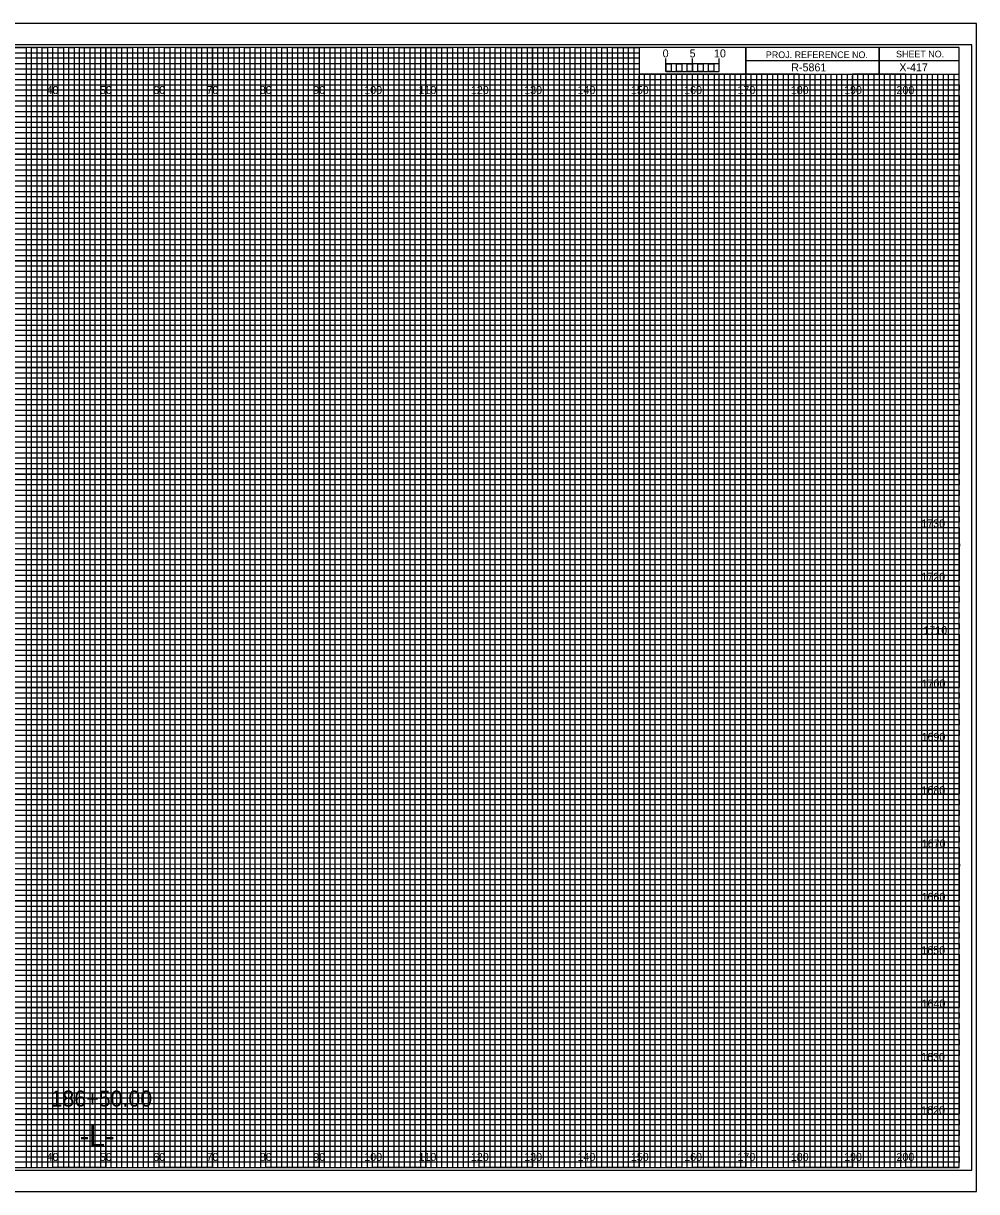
# Model space of a CAD drawing. Extents: x -13 to 323, y -5 to 6154.
# Drawn here: x 144.5 to 323.3, y 2855.5 to 3074.5 of the extents above; entities that cross this region are included whole.
import ezdxf

# ---------------------------------------------------------------- set-up
doc = ezdxf.new("R2010")
doc.units = 0
for name, color, linetype in [('Exist CMT Ground Line', 7, 'Continuous'), ('Prop Horizontal Alignment', 7, 'Continuous'), ('Prop Retaining Wall', 7, 'Continuous'), ('Prop XS Alignment Label', 7, 'Continuous'), ('Prop XS Bar Scale Labels', 7, 'Continuous'), ('Prop XS DDE', 7, 'Continuous'), ('Prop XS DDE Elevations', 7, 'Continuous'), ('Prop XS DDE Slope Text', 7, 'Continuous'), ('Prop XS Earthwork Shape', 7, 'Continuous'), ('Prop XS Elevation Labels', 7, 'Continuous'), ('Prop XS Project Number', 7, 'Continuous'), ('Prop XS Sheet Number', 7, 'Continuous'), ('Prop XS Station Labels', 7, 'Continuous'), ('Raster_Level_0', 7, 'Continuous'), ('Scratch_Level_3', 7, 'Continuous'), ('Sheet Cutting Line CELL', 7, 'Continuous')]:
    doc.layers.add(name, color=color, linetype=linetype)

msp = doc.modelspace()

# ---------------------------------------------------------------- linework, layer by layer
at = {"layer": 'Exist CMT Ground Line'}
for p, q in [((265, 3065.49), (265, 3067.9)), ((265, 3066.9), (265, 3067.9)), ((270, 3065.49), (270, 3067.9)), ((275, 3065.49), (275, 3067.9)), ((275, 3066.9), (275, 3067.9))]:
    msp.add_line(p, q, dxfattribs=at)
for points in [[(275, 3066.9), (265, 3066.9), (265, 3065.49), (275, 3065.49)], [(265, 3066.9), (266, 3066.9), (266, 3065.49), (265, 3065.49)], [(267, 3066.9), (268, 3066.9), (268, 3065.49), (267, 3065.49)], [(269, 3066.9), (270, 3066.9), (270, 3065.49), (269, 3065.49)], [(271, 3066.9), (272, 3066.9), (272, 3065.49), (271, 3065.49)], [(273, 3066.9), (274, 3066.9), (274, 3065.49), (273, 3065.49)]]:
    msp.add_lwpolyline(points, close=True, dxfattribs=at)
at = {"layer": 'Prop Retaining Wall'}
for p, q in [((0, 3069), (260, 3069)), ((260, 3069), (260, 3067.98)), ((260, 3067.98), (0, 3067.98)), ((0, 3067), (260, 3067)), ((260, 3067), (260, 3065.89)), ((260, 3065.89), (0, 3065.89)), ((0, 3064), (320, 3064))]:
    msp.add_line(p, q, dxfattribs=at)
for points in [[(0, 3063), (270, 3063), (320, 3063), (320, 3062), (0, 3062)], [(0, 3061), (320, 3061), (320, 3059), (0, 3059)], [(0, 3058), (320, 3058), (320, 3057), (0, 3056.98)], [(0, 3056), (320, 3056), (320, 3054), (0, 3054)], [(0, 3053), (320, 3053), (320, 3052), (0, 3052)], [(0, 3051), (320, 3051), (320, 3049), (0, 3049)], [(0, 3048), (320, 3048), (320, 3047), (0, 3047)], [(0, 3046), (320, 3046), (320, 3044), (0, 3044)], [(0, 3043), (320, 3043), (320, 3042), (0, 3042)], [(0, 3041), (320, 3041), (320, 3039), (0, 3039)], [(0, 3038), (320, 3038), (320, 3037), (0, 3037)], [(0, 3036), (320, 3036), (320, 3033.95), (320, 3033), (320, 3032), (0, 3032)], [(0, 3034), (320, 3034), (320, 3033), (0, 3033)], [(0, 3031), (320, 3031), (320, 3029), (0, 3029.03)], [(0, 3029.03), (320, 3029), (320, 3028), (0, 3028)], [(0, 3027), (320, 3027), (320, 3026), (0, 3026)], [(0, 3024), (320, 3024), (320, 3023), (0, 3023)], [(0, 3022), (320, 3022), (320, 3021), (0, 3021)], [(-0.07, 3018.89), (320, 3018.89), (320, 3017.88), (-0.07, 3017.88)], [(0, 3017), (320, 3017), (320, 3016), (0, 3016)], [(0, 3014), (320, 3014), (320, 3013), (0, 3013)], [(0, 3012), (320, 3012), (320, 3011), (0, 3011)], [(0, 3009), (320, 3009), (320, 3008), (0, 3008)], [(0, 3007), (320, 3007), (320, 3006), (0, 3006)], [(0, 3004), (320, 3004), (320, 3003), (0, 3003)], [(0, 3002), (320, 3002), (320, 3001), (0, 3001)], [(0, 2999), (320, 2999), (319.99, 2997.98), (0, 2998)], [(0, 2997), (320, 2997), (320, 2996), (0, 2996)], [(0, 2994), (320, 2994), (320, 2993), (0, 2993)], [(0, 2992), (320, 2992), (320, 2991), (0, 2991)], [(0, 2989), (320, 2989), (320, 2988), (0, 2988)], [(0, 2987), (320, 2987), (320, 2986), (0, 2986)], [(0, 2984), (320, 2984), (320, 2983), (0, 2983)], [(0, 2982), (320, 2982), (320, 2981), (0, 2981)], [(0, 2979), (320, 2979), (320, 2978), (0, 2978)], [(0, 2976.99), (320.07, 2976.91), (320, 2976), (0, 2976)], [(0, 2974), (320, 2974), (320, 2973), (0, 2973)], [(0, 2972), (320, 2972), (320, 2971), (0, 2971)], [(0, 2969), (320, 2969), (320, 2968), (0, 2968)], [(0, 2967), (320, 2967), (320, 2966), (0, 2966)], [(0, 2964), (320, 2964), (320, 2963), (0, 2963)], [(0, 2962), (320, 2962), (320, 2961), (0, 2961)], [(0, 2959), (320, 2959), (320, 2958), (0, 2958)], [(0, 2957), (320, 2957), (320, 2956), (0, 2956)], [(0, 2954), (320, 2954), (320, 2953), (0, 2953)], [(0, 2952), (320, 2952), (320, 2951), (0, 2951)], [(0, 2949), (320, 2949), (320, 2948), (0, 2948)], [(0, 2947), (320, 2947), (320, 2946), (0, 2946)], [(0, 2944), (320, 2944), (320, 2943), (0, 2943)], [(0, 2942), (320, 2942), (320, 2941), (0, 2941)], [(0, 2939), (320, 2939), (319.99, 2937.98), (0, 2938)], [(0, 2937), (320, 2937), (320, 2936), (0, 2936)], [(0, 2934), (320, 2934), (320, 2933), (0, 2933)], [(0, 2932), (320, 2932), (320, 2931), (0, 2931)], [(0, 2929), (320, 2929), (320, 2928), (0, 2928)], [(0, 2927), (320, 2927), (320, 2926), (0, 2926)], [(0, 2924), (320, 2924), (320, 2923), (0, 2923)], [(0, 2922), (320, 2922), (320, 2921), (0, 2921)], [(0, 2919), (320, 2919), (320, 2918), (0, 2918)], [(0, 2916.99), (320.07, 2916.91), (320, 2916), (0, 2916)], [(0, 2914), (320, 2914), (320, 2913), (0, 2913)], [(0, 2912), (320, 2912), (320, 2911), (0, 2911)], [(0, 2909), (320, 2909), (320, 2908), (0, 2908)], [(0, 2907), (320, 2907), (320, 2906), (0, 2906)], [(0, 2904), (320, 2904), (320, 2903), (0, 2903)], [(0, 2902), (320, 2902), (320, 2901), (0, 2901)], [(0, 2899), (320, 2899), (320, 2898), (0, 2898)], [(0, 2897), (320, 2897), (320, 2896), (0, 2896)], [(0, 2894), (320, 2894), (320, 2893), (0, 2893)], [(0, 2892), (320, 2892), (320, 2891), (0, 2891)], [(0, 2889), (320, 2889), (320, 2888), (0, 2888)], [(0, 2887), (320, 2887), (320, 2886), (0, 2886)], [(0, 2884), (320, 2884), (320, 2883), (0, 2883)], [(0, 2882), (320, 2882), (320, 2881), (0, 2881)], [(0, 2879), (320, 2879), (320, 2878), (0, 2878)], [(0, 2877), (320, 2877), (320, 2876), (0, 2876)], [(0, 2874), (320, 2874), (320, 2873), (0, 2873)], [(0, 2872), (320, 2872), (320, 2871), (0, 2871)], [(0, 2869), (320, 2869), (320, 2868), (0, 2868)], [(0, 2867), (320, 2867), (320, 2866), (0, 2866)], [(0, 2864), (320, 2864), (320, 2863), (0, 2863)], [(0, 2862), (320, 2862), (320, 2861), (0, 2861)]]:
    msp.add_lwpolyline(points, dxfattribs=at)
at = {"layer": 'Prop XS Alignment Label'}
for p, q in [((305, 3070), (305, 3065)), ((305, 3065), (305, 3070)), ((280, 3067.5), (280, 3065)), ((320, 3067.49), (280, 3067.49)), ((280, 3065), (320, 3065))]:
    msp.add_line(p, q, dxfattribs=at)
for points in [[(320, 3070), (0, 3070), (0, 2860), (320, 2860)], [(280, 3070), (260, 3070), (260, 3065.03), (280, 3065.03)], [(320, 3070), (280, 3070), (280, 3065), (320, 3065)]]:
    msp.add_lwpolyline(points, close=True, dxfattribs=at)
at = {"layer": 'Prop XS DDE'}
msp.add_lwpolyline([(-13.4, 2855.5), (323.3, 2855.5), (323.3, 3074.5), (-13.4, 3074.5)], close=True, dxfattribs=at)
at = {"layer": 'Prop XS DDE Elevations'}
for p, q in [((150, 2860), (150, 3070)), ((160, 2860), (160, 3070)), ((170, 2860), (170, 3070)), ((180, 2860), (180, 3070)), ((190, 2860), (190, 3070)), ((200, 2860), (200, 3070)), ((210, 2860), (210, 3070)), ((220, 2860), (220, 3070)), ((230, 2860), (230, 3070)), ((240, 2860), (240, 3070)), ((250, 2860), (250, 3070)), ((260, 2860), (260, 3064.69)), ((270, 2860), (270, 3064.69)), ((280, 2860), (280, 3064.69)), ((290, 2860), (290, 3064.69)), ((300, 2860), (300, 3064.69)), ((310, 2860), (310, 3064.69)), ((0, 3060), (320, 3060)), ((0, 3050), (320, 3050)), ((0, 3040), (320, 3040)), ((0, 3030), (320, 3030)), ((0, 3020), (320, 3020)), ((0, 3010), (320, 3010)), ((0, 3000), (320, 3000)), ((0, 2990), (320, 2990)), ((0, 2980), (320, 2980)), ((0, 2970), (320, 2970)), ((0, 2960), (320, 2960)), ((0, 2950), (320, 2950)), ((0, 2940), (320, 2940)), ((0, 2930), (320, 2930)), ((0, 2920), (320, 2920)), ((0, 2910), (320, 2910)), ((0, 2900), (320, 2900)), ((0, 2890), (320, 2890)), ((0, 2880), (320, 2880)), ((0, 2870), (320, 2870))]:
    msp.add_line(p, q, dxfattribs=at)
at = {"layer": 'Prop XS DDE Slope Text'}
msp.add_lwpolyline([(-10.8, 2859.5), (322.4, 2859.5), (322.4, 3070.5), (-10.8, 3070.5)], close=True, dxfattribs=at)
at = {"layer": 'Prop XS Earthwork Shape'}
for p, q in [((150, 3070), (140, 3070)), ((150, 2860), (150, 3070)), ((170, 3070), (160, 3070)), ((160, 3070), (160, 2860)), ((170, 2860), (170, 3070)), ((190, 3070), (180, 3070)), ((180, 3070), (180, 2860)), ((190, 2860), (190, 3070)), ((210, 3070), (200, 3070)), ((200, 3070), (200, 2860)), ((210, 2860), (210, 3070)), ((230, 3070), (220, 3070)), ((220, 3070), (220, 2860)), ((230, 2860), (230, 3070)), ((250, 3070), (240, 3070)), ((240, 3070), (240, 2860)), ((250, 2860), (250, 3070)), ((260, 3070), (260, 2860)), ((270, 2860), (270, 3065)), ((290, 3065), (280, 3065)), ((280, 3065), (280, 2860)), ((290, 2860), (290, 3065)), ((310, 3065), (300, 3065)), ((300, 3065), (300, 2860)), ((310, 2860), (310, 3065)), ((160, 2860), (150, 2860)), ((180, 2860), (170, 2860)), ((200, 2860), (190, 2860)), ((220, 2860), (210, 2860)), ((240, 2860), (230, 2860)), ((260, 2860), (250, 2860)), ((280, 2860), (270, 2860)), ((300, 2860), (290, 2860)), ((320, 2860), (310, 2860)), ((320, 2860), (320, 2860))]:
    msp.add_line(p, q, dxfattribs=at)
for points in [[(0, 3060), (320, 3060), (320, 3050), (0, 3050)], [(0, 3040), (320, 3040), (320, 3030), (0, 3030)], [(0, 3020), (320, 3020), (320, 3010), (0, 3010)], [(0, 3000), (320, 3000), (320, 2990), (0, 2990)], [(0, 2980), (320, 2980), (320, 2970), (0, 2970)], [(0, 2960), (320, 2960), (320, 2950), (0, 2950)], [(0, 2940), (320, 2940), (320, 2930), (0, 2930)], [(0, 2920), (320, 2920), (320, 2910), (0, 2910)], [(0, 2900), (320, 2900), (320, 2890), (0, 2890)], [(0, 2880), (320, 2880), (320, 2870), (0, 2870)]]:
    msp.add_lwpolyline(points, dxfattribs=at)
at = {"layer": 'Prop XS Elevation Labels'}
for p, q in [((267, 3065), (266.01, 3065)), ((266.01, 3065), (266.01, 2860)), ((267, 2860), (267, 3065)), ((269, 3065), (268, 3065)), ((268, 3065), (268, 2860)), ((269, 2860), (269, 3065)), ((266.01, 2860), (265, 2860)), ((268, 2860), (267, 2860))]:
    msp.add_line(p, q, dxfattribs=at)
for points in [[(145, 2860), (146, 2860), (146, 3070), (147, 3070), (147, 2860)], [(147, 2860), (148, 2860), (148, 3070), (149, 3070), (149, 2860)], [(150, 2860), (151, 2860), (151, 3070), (152, 3070), (152, 2860)], [(152, 2860), (153, 2860), (153, 3070), (154, 3070), (154, 2860)], [(155, 2860), (156, 2860), (156, 3070), (157, 3070), (157, 2860)], [(157, 2860), (158, 2860), (158, 3070), (159, 3070), (159, 2860)], [(160, 2860), (161, 2860), (161, 3070), (162, 3070), (162, 2860)], [(162, 2860), (163, 2860), (163, 3070), (164, 3070), (164, 2860)], [(165, 2860), (166, 2860), (166, 3070), (167, 3070), (167, 2860)], [(167, 2860), (168, 2860), (168, 3070), (169, 3070), (169, 2860)], [(170, 2860), (171, 2860), (171, 3070), (172, 3070), (172, 2860)], [(172, 2860), (173, 2860), (173, 3070), (174, 3070), (174, 2860)], [(175, 2860), (176, 2860), (176, 3070), (177, 3070), (177, 2860)], [(177, 2860), (178, 2860), (178, 3070), (179, 3070), (179, 2860)], [(180, 2860), (181, 2860), (181, 3070), (182, 3070), (182, 2860)], [(182, 2860), (183, 2860), (183, 3070), (184, 3070), (184, 2860)], [(185, 2860), (186, 2860), (186, 3070), (187, 3070), (187, 2860)], [(187, 2860), (188, 2860), (188, 3070), (189, 3070), (189, 2860)], [(190, 2860), (191, 2860), (191, 3070), (192, 3070), (192, 2860)], [(192, 2860), (193, 2860), (193, 3070), (194, 3070), (194, 2860)], [(195, 2860), (196, 2860), (196, 3070), (197, 3070), (197, 2860)], [(197, 2860), (198, 2860), (198, 3070), (199, 3070), (199, 2860)], [(200, 2860), (201, 2860), (201, 3070), (202, 3070), (202, 2860)], [(202, 2860), (203, 2860), (203, 3070), (204, 3070), (204, 2860)], [(205, 2860), (206, 2860), (206, 3070), (207, 3070), (207, 2860)], [(207, 2860), (208, 2860), (208, 3070), (209, 3070), (209, 2860)], [(210, 2860), (211, 2860), (211, 3070), (212, 3070), (212, 2860)], [(212, 2860), (213, 2860), (213, 3070), (214, 3070), (214, 2860)], [(215, 2860), (216, 2860), (216, 3070), (217, 3070), (217, 2860)], [(217, 2860), (218, 2860), (218, 3070), (219, 3070), (219, 2860)], [(220, 2860), (221, 2860), (221, 3070), (222, 3070), (222, 2860)], [(222, 2860), (223, 2860), (223, 3070), (224, 3070), (224, 2860)], [(225, 2860), (226, 2860), (226, 3070), (227, 3070), (227, 2860)], [(227, 2860), (228, 2860), (228, 3070), (229, 3070), (229, 2860)], [(230, 2860), (231, 2860), (231, 3070), (232, 3070), (232, 2860)], [(232, 2860), (233, 2860), (233, 3070), (234, 3070), (234, 2860)], [(235, 2860), (236, 2860), (236, 3070), (237, 3070), (237, 2860)], [(237, 2860), (238, 2860), (238, 3070), (239, 3070), (239, 2860)], [(240, 2860), (241, 2860), (241, 3070), (242, 3070), (242, 2860)], [(242, 2860), (243, 2860), (243, 3070), (244, 3070), (244, 2860)], [(245, 2860), (246, 2860), (246, 3070), (247, 3070), (247, 2860)], [(247, 2860), (248, 2860), (248, 3070), (249, 3070), (249, 2860)], [(250, 2860), (251, 2860), (251, 3070), (252, 3070), (252, 2860)], [(252, 2860), (253, 2860), (253, 3070), (254, 3070), (254, 2860)], [(255, 2860), (256, 2860), (256, 3070), (257, 3070), (257, 2860)], [(257, 2860), (258, 2860), (258, 3070), (259, 3070), (259, 2860)], [(260, 2860), (261, 2860), (261, 3065), (262.02, 3065), (262.02, 2860)], [(262, 2860), (263, 2860), (263, 3065), (263.99, 3065), (263.99, 2860)], [(270, 2860), (270.98, 2860), (270.98, 3065), (272, 3065), (272, 2860)], [(272, 2860), (273, 2860), (273, 3065), (274.05, 3065), (274.05, 2860)], [(275, 2860), (276, 2860), (276, 3065), (277, 3065), (277, 2860)], [(277, 2860), (278, 2860), (278, 3065), (279, 3065), (279, 2860)], [(280, 2860), (281, 2860), (281, 3065), (282, 3065), (282, 2860)], [(282, 2860), (283, 2860), (283, 3065), (284, 3065), (284, 2860)], [(285, 2860), (286, 2860), (286, 3065), (287, 3065), (287, 2860)], [(287, 2860), (288, 2860), (288, 3065), (289, 3065), (289, 2860)], [(290, 2860), (291, 2860), (291, 3065), (292, 3065), (292, 2860)], [(292, 2860), (293, 2860), (293, 3065), (294, 3065), (294, 2860)], [(295, 2860), (296, 2860), (296, 3065), (297, 3065), (297, 2860)], [(297, 2860), (298, 2860), (298, 3065), (299, 3065), (299, 2860)], [(300, 2860), (301, 2860), (301, 3065), (302, 3065), (302, 2860)], [(302, 2860), (303, 2860), (303, 3065), (304, 3065), (304, 2860)], [(305, 2860), (306, 2860), (306, 3065), (307, 3065), (307, 2860)], [(307, 2860), (308, 2860), (308, 3065), (309, 3065), (309, 2860)], [(310, 2860), (311, 2860), (311, 3065), (312, 3065), (312, 2860)], [(312, 2860), (313, 2860), (313, 3065), (314, 3065), (314, 2860)], [(315, 2860), (316, 2860), (316, 3065), (317, 3065), (317, 2860)], [(317, 2860), (318, 2860), (318, 3065), (319, 3065), (319, 2860)]]:
    msp.add_lwpolyline(points, dxfattribs=at)
at = {"layer": 'Prop XS Station Labels'}
for points in [[(135, 3070), (145, 3070), (145, 2860), (155, 2860), (155, 3070), (165, 3070), (165, 2860), (175, 2860), (175, 3070), (185, 3070), (185, 2860), (195, 2860), (195, 3070), (205, 3070), (205, 2860), (215, 2860), (215, 3070), (225, 3070), (225, 2860), (235, 2860), (235, 3070), (245, 3070), (245, 2860), (255, 2860), (255, 3070), (259.93, 3070), (260, 3070), (260, 3065), (264.99, 3065), (264.99, 2860), (275, 2860), (275, 3065), (285, 3065), (285, 2860), (295, 2860), (295, 3065), (305, 3065), (305, 2860), (315, 2860), (315, 3065)], [(0, 3065), (275, 3065)], [(0, 3045), (320, 3045), (320, 3055), (0, 3055)], [(0, 3025), (320, 3025), (320, 3035), (0, 3035)], [(0, 3005), (320, 3005), (320, 3015), (0, 3015)], [(0, 2985), (320, 2985), (320, 2995), (0, 2995)], [(0, 2965), (320, 2965), (320, 2975), (0, 2975)], [(0, 2945), (320, 2945), (320, 2955), (0, 2955)], [(0, 2925), (320, 2925), (320, 2935), (0, 2935)], [(0, 2905), (320, 2905), (320, 2915), (0, 2915)], [(0, 2885), (320, 2885), (320, 2895), (0, 2895)], [(0, 2865), (320, 2865), (320, 2875), (0, 2875)]]:
    msp.add_lwpolyline(points, dxfattribs=at)
at = {"layer": 'Sheet Cutting Line CELL'}
for p, q in [((323.3, 3074.5), (-13.4, 3074.5)), ((-13.4, 2855.5), (323.3, 2855.5))]:
    msp.add_line(p, q, dxfattribs=at)

# ---------------------------------------------------------------- texts
at = {"layer": 'Exist CMT Ground Line'}
msp.add_text('0', height=1.5, dxfattribs=at).set_placement((264.41, 3068.12))
at = {"layer": 'Prop Horizontal Alignment'}
msp.add_text('186+50.00', height=3, dxfattribs=at).set_placement((149.59, 2871.45))
at = {"layer": 'Prop XS Alignment Label'}
for s, height, p in [('PROJ. REFERENCE NO.', 1.25, (283.77, 3067.99)), ('SHEET NO.', 1.25, (308.19, 3068.12)), ('-L-', 4, (155.06, 2864))]:
    msp.add_text(s, height=height, dxfattribs=at).set_placement(p)
at = {"layer": 'Prop XS Bar Scale Labels'}
for s, p in [('5', (269.47, 3068.12)), ('10', (274.04, 3068.12))]:
    msp.add_text(s, height=1.5, dxfattribs=at).set_placement(p)
at = {"layer": 'Prop XS Project Number'}
msp.add_text('R-5861', height=1.5, dxfattribs=at).set_placement((288.53, 3065.5))
at = {"layer": 'Prop XS Sheet Number'}
msp.add_text('X-417', height=1.5, dxfattribs=at).set_placement((308.8, 3065.51))
at = {"layer": 'Raster_Level_0'}
for s, p in [('40', (148.86, 3061.25)), ('50', (158.86, 3061.25)), ('60', (168.86, 3061.25)), ('70', (178.86, 3061.25)), ('80', (188.86, 3061.25)), ('90', (198.86, 3061.25)), ('100', (208.44, 3061.25)), ('110', (218.62, 3061.25)), ('120', (228.44, 3061.25)), ('130', (238.44, 3061.25)), ('140', (248.44, 3061.25)), ('150', (258.44, 3061.25)), ('160', (268.44, 3061.25)), ('170', (278.44, 3061.25)), ('180', (288.44, 3061.25)), ('190', (298.44, 3061.25)), ('200', (308.26, 3061.25)), ('40', (148.86, 2861.25)), ('50', (158.86, 2861.25)), ('60', (168.86, 2861.25)), ('70', (178.86, 2861.25)), ('80', (188.86, 2861.25)), ('90', (198.86, 2861.25)), ('100', (208.44, 2861.25)), ('110', (218.62, 2861.25)), ('120', (228.44, 2861.25)), ('130', (238.44, 2861.25)), ('140', (248.44, 2861.25)), ('150', (258.44, 2861.25)), ('160', (268.44, 2861.25)), ('170', (278.44, 2861.25)), ('180', (288.44, 2861.25)), ('190', (298.44, 2861.25)), ('200', (308.26, 2861.25))]:
    msp.add_text(s, height=1.5, dxfattribs=at).set_placement(p)
at = {"layer": 'Scratch_Level_3'}
for s, p in [('1730', (312.92, 2980)), ('1720', (312.93, 2970)), ('1710', (313.31, 2960)), ('1700', (312.98, 2950)), ('1690', (312.97, 2940)), ('1680', (312.95, 2930)), ('1670', (313, 2920)), ('1660', (312.97, 2910)), ('1650', (312.92, 2900)), ('1640', (312.97, 2890)), ('1630', (312.89, 2880)), ('1620', (312.9, 2870))]:
    msp.add_text(s, height=1.5, dxfattribs=at).set_placement(p)

doc.saveas('drawing.dxf')
